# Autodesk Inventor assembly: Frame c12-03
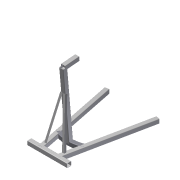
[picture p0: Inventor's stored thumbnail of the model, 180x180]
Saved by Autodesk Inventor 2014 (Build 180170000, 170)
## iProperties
Created: 2011-01
Part Number: Frame c12-03
Document SubType Name: Assembly
Designer: Thom Tremblay
_FrameDoc: Frame Assembly
_Version: 15.0.0
Author: Thom Tremblay
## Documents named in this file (18)
- C:\Inventor 2014 Essentials\Assemblies\Chapter 12\Frame\Frame c12-03.iam
- C:\Inventor 2014 Essentials\Assemblies\Chapter 12\Frame\Skeleton-c12-03.ipt
- C:\Inventor 2014 Essentials\Assemblies\Chapter 12\Frame\ANSI 3x3x3_16 00000007.ipt
- ANSI 3x3x3_16 00000007.ipt
- C:\Inventor 2014 Essentials\Assemblies\Chapter 12\Frame\ANSI 3x3x3_16 00000009.ipt
- ANSI 3x3x3_16 00000009.ipt
- C:\Inventor 2014 Essentials\Assemblies\Chapter 12\Frame\ANSI 3x3x3_16 00000010.ipt
- ANSI 3x3x3_16 00000010.ipt
- C:\Inventor 2014 Essentials\Assemblies\Chapter 12\Frame\ANSI 3x3x3_16 00000012.ipt
- ANSI 3x3x3_16 00000012.ipt
- C:\Inventor 2014 Essentials\Assemblies\Chapter 12\Frame\ANSI L 1.5 x 1.5 x 3_16 00000013.ipt
- ANSI L 1.5 x 1.5 x 3_16 00000013.ipt
- C:\Inventor 2014 Essentials\Assemblies\Chapter 12\Frame\ANSI L 1.5 x 1.5 x 3_16 00000014.ipt
- ANSI L 1.5 x 1.5 x 3_16 00000014.ipt
- C:\Inventor 2014 Essentials\Assemblies\Chapter 12\Frame\ANSI 3x3x3_16 00000053.ipt
- ANSI 3x3x3_16 00000011.ipt
- C:\Inventor 2014 Essentials\Assemblies\Chapter 12\Frame\ANSI 3x3x3_16 00000056.ipt
- ANSI 3x3x3_16 00000056.ipt
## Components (9 placed, 9 different names)
1. Frame Reference Model
2. ANSI 3x3x3_16 00000007:1
3. ANSI 3x3x3_16 00000009:1
4. ANSI 3x3x3_16 00000010:1
5. ANSI 3x3x3_16 00000012:1
6. ANSI L 1.5 x 1.5 x 3_16 00000013:1
7. ANSI L 1.5 x 1.5 x 3_16 00000014:1
8. ANSI 3x3x3_16 00000011:1
9. ANSI 3x3x3_16 00000056:1
